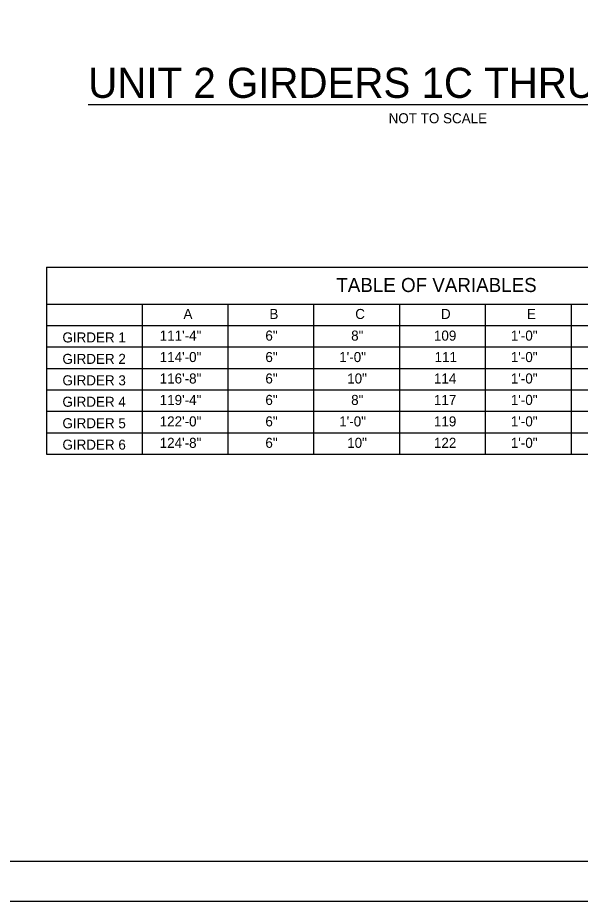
# Model space of a CAD drawing. Extents: x -305 to -161, y -187 to -99.
# Drawn here: x -251.38 to -223.35, y -187.49 to -143.49 of the extents above; entities that cross this region are included whole.
import ezdxf

# ---------------------------------------------------------------- set-up
doc = ezdxf.new("R2010")
doc.units = 0
for name, color, linetype in [('BR_AUTO DIMENSION', 7, 'Continuous'), ('BR_BORDER LINES', 7, 'Continuous'), ('BR_TEXT', 7, 'Continuous'), ('Level 31', 7, 'Continuous')]:
    doc.layers.add(name, color=color, linetype=linetype)

msp = doc.modelspace()

# ---------------------------------------------------------------- linework, layer by layer
at = {"layer": 'BR_AUTO DIMENSION'}
for p, q in [((-249.938, -155.913), (-249.938, -165.222)), ((-249.938, -155.913), (-210.987, -155.913)), ((-249.938, -157.747), (-210.987, -157.747)), ((-245.184, -157.747), (-245.184, -165.222)), ((-240.91, -157.747), (-240.91, -165.222)), ((-236.635, -157.747), (-236.635, -165.222)), ((-232.36, -157.747), (-232.36, -165.222)), ((-228.085, -157.747), (-228.085, -165.222)), ((-223.811, -157.747), (-223.811, -165.222)), ((-249.938, -158.815), (-210.987, -158.815)), ((-249.938, -159.882), (-210.987, -159.882)), ((-249.938, -160.95), (-210.987, -160.95)), ((-249.938, -162.018), (-210.987, -162.018)), ((-249.938, -163.086), (-210.987, -163.086)), ((-249.938, -164.154), (-210.987, -164.154)), ((-249.938, -165.222), (-210.987, -165.222))]:
    msp.add_line(p, q, dxfattribs=at)
at = {"layer": 'BR_BORDER LINES'}
msp.add_line((-297.843, -185.489), (-163.178, -185.489), dxfattribs=at)
at = {"layer": 'BR_TEXT'}
msp.add_line((-247.874, -147.82), (-213.173, -147.82), dxfattribs=at)
at = {"layer": 'Level 31'}
msp.add_lwpolyline([(-305.176, -187.489), (-161.176, -187.489), (-161.176, -99.489), (-305.176, -99.489)], close=True, dxfattribs=at)

# ---------------------------------------------------------------- texts
at = {"layer": 'BR_TEXT'}
for s, height, p in [('UNIT 2 GIRDERS 1C THRU 6C ELEVATION', 1.5, (-247.865, -147.483)), ('NOT TO SCALE', 0.5, (-232.898, -148.747)), ('TABLE OF VARIABLES', 0.69972, (-235.505, -157.15))]:
    msp.add_text(s, height=height, dxfattribs=at).set_placement(p)
for s, p in [('A', (-243.12, -158.492)), ('B', (-238.837, -158.492)), ('C', (-234.563, -158.492)), ('D', (-230.29, -158.492)), ('E', (-226.012, -158.492)), ('GIRDER 1', (-249.151, -159.661)), ('111\'-4"', (-244.306, -159.57)), ('6"', (-239.039, -159.57)), ('8"', (-234.764, -159.57)), ('109', (-230.641, -159.57)), ('1\'-0"', (-226.81, -159.57)), ('114\'-0"', (-244.306, -160.637)), ('6"', (-239.039, -160.637)), ('1\'-0"', (-235.36, -160.637)), ('111', (-230.608, -160.637)), ('1\'-0"', (-226.81, -160.637)), ('GIRDER 2', (-249.151, -160.729)), ('GIRDER 3', (-249.151, -161.796)), ('116\'-8"', (-244.306, -161.705)), ('6"', (-239.039, -161.705)), ('10"', (-234.963, -161.705)), ('114', (-230.641, -161.705)), ('1\'-0"', (-226.81, -161.705)), ('GIRDER 4', (-249.151, -162.864)), ('119\'-4"', (-244.306, -162.773)), ('6"', (-239.039, -162.773)), ('8"', (-234.764, -162.773)), ('117', (-230.641, -162.773)), ('1\'-0"', (-226.81, -162.773)), ('GIRDER 5', (-249.151, -163.932)), ('122\'-0"', (-244.306, -163.841)), ('6"', (-239.039, -163.841)), ('1\'-0"', (-235.36, -163.841)), ('119', (-230.641, -163.841)), ('1\'-0"', (-226.81, -163.841)), ('GIRDER 6', (-249.151, -165)), ('124\'-8"', (-244.306, -164.909)), ('6"', (-239.039, -164.909)), ('10"', (-234.963, -164.909)), ('122', (-230.641, -164.909)), ('1\'-0"', (-226.81, -164.909))]:
    msp.add_text(s, height=0.5, rotation=360, dxfattribs=at).set_placement(p)

doc.saveas('drawing.dxf')
